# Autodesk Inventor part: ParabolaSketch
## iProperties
Shininess: 64.0
Length Units: 11272
Angle Units: 11279
Time Units: 11290
Mass Units: 11286
Length Display Precision: 3
Angle Display Precision: 2
Compacted: True
Part Number: ParabolaSketch
Document SubType Name: Modeling
Created: 2004-06
Designer: Administrator
Manufacturer: Standard
Standards Organization: Custom
Density: 0.0
Volumn: 0.0
Area: 0.0
PropertySet Name: Model Information
Control State: 0
Master: False
Checked Out: False
Author: Administrator
